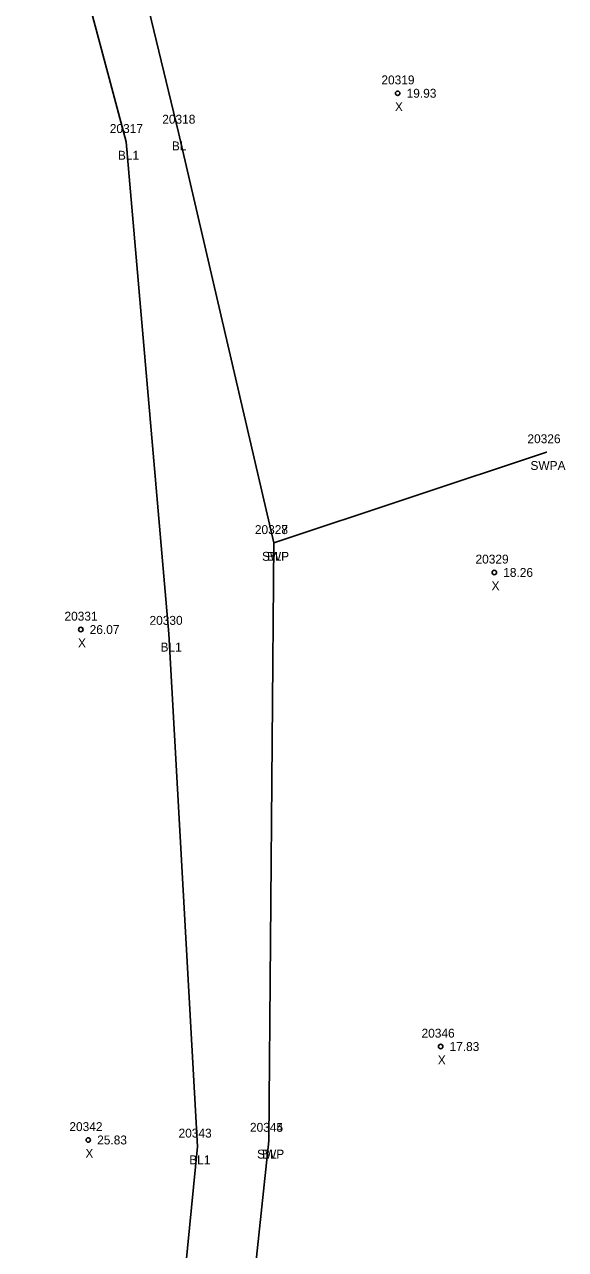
# Model space of a CAD drawing. Extents: x 2432729 to 2433340, y 684958 to 688103.
# Drawn here: x 2433168.9 to 2433229.6, y 686200.1 to 686337.6 of the extents above; entities that cross this region are included whole.
import ezdxf

# ---------------------------------------------------------------- set-up
doc = ezdxf.new("R2010")
doc.units = 0
for name, color, linetype in [('RD_DTM_BkLn1', 7, 'Continuous'), ('RD_EX_H2O', 7, 'Continuous'), ('RD_EX_H2O_txCode', 7, 'Continuous'), ('RD_Sketch8', 7, 'Continuous'), ('RD_SMD_Locator', 7, 'Continuous'), ('RD_SMD_Misc', 7, 'Continuous')]:
    doc.layers.add(name, color=color, linetype=linetype)

msp = doc.modelspace()

# ---------------------------------------------------------------- linework, layer by layer
at = {"layer": 'RD_DTM_BkLn1'}
for points in [[(2433121.01, 686546.89), (2433138.81, 686483.59), (2433156.33, 686436.44), (2433172.33, 686382.63), (2433186.16, 686325.49), (2433196.85, 686279.41), (2433196.3, 686212.3), (2433190.98, 686162.16), (2433188.39, 686102.75), (2433180.42, 686073.48), (2433172.96, 686068.93), (2433166.53, 686062.55), (2433152.82, 686065.09)], [(2433099.45, 686534.09), (2433116.42, 686534.99), (2433132.92, 686481.52), (2433149.46, 686435.57), (2433165.09, 686381.24), (2433180.28, 686324.44), (2433185.06, 686269.22), (2433188.28, 686211.65), (2433183.39, 686161.81), (2433176.18, 686106.19), (2433174.91, 686080.31), (2433163.5, 686077.21), (2433155.14, 686078.25)]]:
    msp.add_lwpolyline(points, dxfattribs=at)
at = {"layer": 'RD_EX_H2O'}
msp.add_lwpolyline([(2433227.48, 686289.61), (2433196.85, 686279.41), (2433196.3, 686212.3), (2433190.98, 686162.16), (2433188.39, 686102.75), (2433180.42, 686073.48), (2433172.96, 686068.93), (2433166.53, 686062.55)], dxfattribs=at)
at = {"layer": 'RD_SMD_Locator'}
for centre, radius in [((2433210.77, 686329.9), 0.25), ((2433186.16, 686325.49), 0.001), ((2433180.28, 686324.44), 0.001), ((2433227.48, 686289.61), 0.001), ((2433196.85, 686279.41), 0.001), ((2433196.85, 686279.41), 0.001), ((2433221.62, 686276.1), 0.25), ((2433175.18, 686269.69), 0.25), ((2433185.06, 686269.22), 0.001), ((2433215.59, 686222.87), 0.25), ((2433176.02, 686212.38), 0.25), ((2433196.3, 686212.3), 0.001), ((2433196.3, 686212.3), 0.001), ((2433188.28, 686211.65), 0.001)]:
    msp.add_circle(centre, radius, dxfattribs=at)

# ---------------------------------------------------------------- texts
at = {"layer": 'RD_EX_H2O_txCode'}
for s, p in [('20326', (2433225.34, 686290.61)), ('SWPA', (2433225.68, 686287.61)), ('20328', (2433194.73, 686280.41)), ('SWP', (2433195.53, 686277.41)), ('20344', (2433194.18, 686213.3)), ('SWP', (2433194.98, 686210.3))]:
    msp.add_text(s, height=1, dxfattribs=at).set_placement(p)
at = {"layer": 'RD_Sketch8'}
for s, p in [('20319', (2433208.94, 686330.9)), ('19.93', (2433211.77, 686329.4)), ('X', (2433210.46, 686327.9)), ('20329', (2433219.51, 686277.1)), ('18.26', (2433222.62, 686275.6)), ('X', (2433221.31, 686274.1)), ('20331', (2433173.35, 686270.69)), ('26.07', (2433176.18, 686269.19)), ('X', (2433174.87, 686267.69)), ('20346', (2433213.45, 686223.87)), ('17.83', (2433216.59, 686222.37)), ('X', (2433215.27, 686220.87)), ('20342', (2433173.9, 686213.38)), ('25.83', (2433177.02, 686211.88)), ('X', (2433175.7, 686210.38))]:
    msp.add_text(s, height=1, dxfattribs=at).set_placement(p)
at = {"layer": 'RD_SMD_Misc'}
for s, p in [('20318', (2433184.33, 686326.49)), ('20317', (2433178.44, 686325.44)), ('BL1', (2433179.35, 686322.44)), ('BL', (2433185.41, 686323.49)), ('20327', (2433194.73, 686280.41)), ('BL', (2433196.09, 686277.41)), ('20330', (2433182.9, 686270.22)), ('BL1', (2433184.14, 686267.22)), ('20343', (2433186.16, 686212.65)), ('20345', (2433194.18, 686213.3)), ('BL1', (2433187.36, 686209.65)), ('BL', (2433195.54, 686210.3))]:
    msp.add_text(s, height=1, dxfattribs=at).set_placement(p)

doc.saveas('drawing.dxf')
